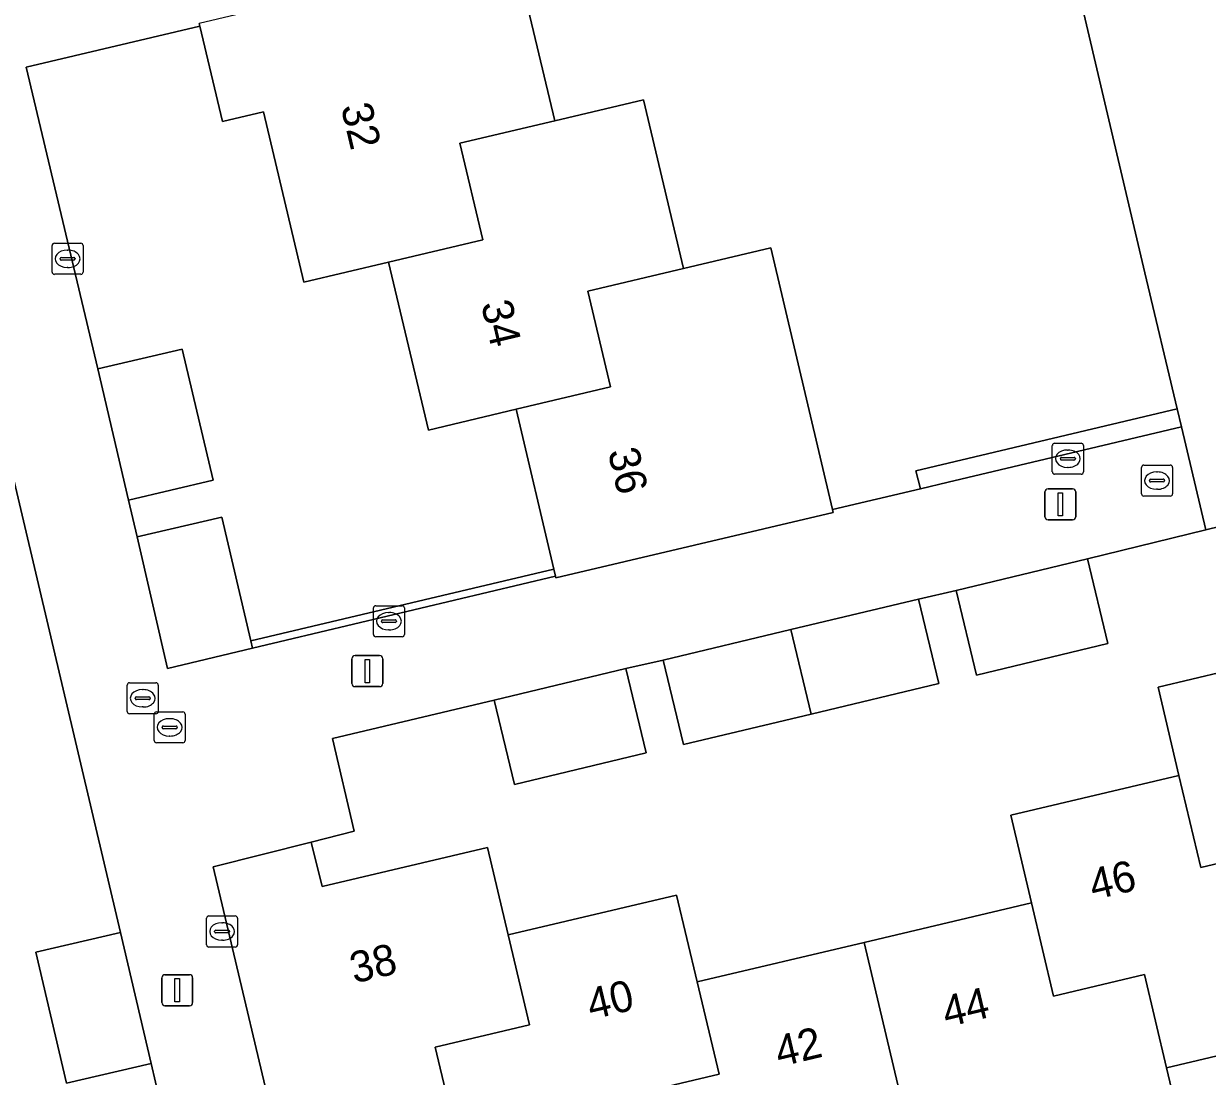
# Model space of a CAD drawing. Extents: x 158031 to 159244, y 380104 to 381214.
# Drawn here: x 158665.32 to 158703.48, y 380430.23 to 380464.17 of the extents above; entities that cross this region are included whole.
import ezdxf

# ---------------------------------------------------------------- set-up
doc = ezdxf.new("R2010")
doc.units = 0
for name, color, linetype in [('IMGEO_Erf', 7, 'Continuous'), ('IMGEO_Groenvoorziening', 7, 'Continuous'), ('IMGEO_Haag', 7, 'Continuous'), ('IMGEO_Hek', 7, 'Continuous'), ('IMGEO_Kolk', 7, 'Continuous'), ('IMGEO_Lichtmast', 7, 'Continuous'), ('IMGEO_Muur', 7, 'Continuous'), ('IMGEO_Pand', 7, 'Continuous'), ('IMGEO_Pand_nummerreeks', 7, 'Continuous'), ('IMGEO_Rioolput', 7, 'Continuous'), ('IMGEO_Voetpad_open', 7, 'Continuous')]:
    doc.layers.add(name, color=color, linetype=linetype)

msp = doc.modelspace()

# ---------------------------------------------------------------- linework, layer by layer
at = {"layer": 'IMGEO_Erf'}
for points in [[(158698.077, 380470.54), (158695.304, 380469.884), (158687.271, 380467.982), (158681.122, 380466.593), (158682.444, 380461.045), (158685.304, 380461.722), (158686.594, 380456.28), (158689.406, 380456.946), (158691.395, 380448.507), (158694.234, 380449.177), (158694.082, 380449.756), (158702.507, 380451.76), (158701.464, 380456.145)], [(158682.408, 380446.591), (158681.194, 380451.741), (158678.369, 380451.071), (158677.086, 380456.482), (158674.354, 380455.835), (158673.051, 380461.332), (158671.732, 380461.02), (158670.999, 380464.096), (158665.396, 380462.768), (158667.707, 380453.042), (158670.434, 380453.683), (158671.427, 380449.453), (158668.7, 380448.812), (158668.978, 380447.633), (158671.707, 380448.262), (158672.644, 380444.272)]]:
    msp.add_lwpolyline(points, close=True, dxfattribs=at)
for points in [[(158669.709, 380429.443), (158669.428, 380430.652), (158666.701, 380430.014), (158665.714, 380434.238), (158668.44, 380434.875), (158663.891, 380454.12), (158661.166, 380453.48), (158660.172, 380457.711), (158662.898, 380458.351), (158662.603, 380459.561), (158659.878, 380458.917), (158658.903, 380463.042), (158657.929, 380467.167)], [(158709.015, 380449.219), (158703.434, 380447.849), (158699.622, 380446.914), (158700.278, 380444.192), (158696.039, 380443.171), (158695.383, 380445.893), (158694.174, 380445.62), (158694.824, 380442.896), (158690.708, 380441.915), (158686.592, 380440.933), (158685.942, 380443.657), (158684.731, 380443.382), (158685.386, 380440.66), (158681.146, 380439.639), (158680.49, 380442.361), (158675.272, 380441.13), (158675.971, 380438.133), (158674.586, 380437.78), (158674.943, 380436.351), (158680.276, 380437.615), (158680.944, 380434.793), (158686.372, 380436.079), (158687.036, 380433.277), (158692.422, 380434.553), (158697.811, 380435.83), (158697.143, 380438.651), (158702.566, 380439.936), (158701.892, 380442.78), (158707.32, 380444.067)], [(158750.754, 380444.95), (158748.003, 380444.298), (158748.681, 380441.436), (158742.908, 380440.068), (158742.225, 380442.949), (158736.76, 380441.654), (158736.076, 380444.542), (158730.78, 380443.287), (158725.382, 380442.008), (158726.053, 380439.177), (158720.687, 380437.905), (158721.385, 380434.963), (158715.603, 380433.593), (158714.896, 380436.577), (158712.343, 380435.972), (158706.887, 380434.679), (158707.572, 380431.787), (158702.164, 380430.506), (158702.795, 380427.844)]]:
    msp.add_lwpolyline(points, dxfattribs=at)
at = {"layer": 'IMGEO_Groenvoorziening'}
msp.add_lwpolyline([(158702.646, 380451.176), (158702.507, 380451.76), (158694.082, 380449.756), (158694.234, 380449.177), (158695.123, 380449.387)], close=True, dxfattribs=at)
at = {"layer": 'IMGEO_Haag'}
msp.add_lwpolyline([(158702.646, 380451.176), (158702.507, 380451.76), (158694.082, 380449.756), (158694.234, 380449.177), (158695.123, 380449.387)], close=True, dxfattribs=at)
at = {"layer": 'IMGEO_Hek'}
msp.add_lwpolyline([(158691.395, 380448.507), (158694.234, 380449.177)], dxfattribs=at)
at = {"layer": 'IMGEO_Kolk'}
for p, q in [((158666.234, 380456.167), (158666.234, 380457.019)), ((158666.309, 380457.093), (158667.161, 380457.093)), ((158666.722, 380456.873), (158666.747, 380456.873)), ((158667.235, 380457.019), (158667.235, 380456.167)), ((158666.493, 380456.587), (158666.493, 380456.599)), ((158666.931, 380456.55), (158666.533, 380456.55)), ((158666.536, 380456.636), (158666.934, 380456.636)), ((158666.977, 380456.599), (158666.977, 380456.587)), ((158667.161, 380456.093), (158666.309, 380456.093)), ((158666.745, 380456.313), (158666.72, 380456.313)), ((158698.484, 380449.722), (158698.484, 380450.574)), ((158698.559, 380450.648), (158699.411, 380450.648)), ((158698.972, 380450.428), (158698.997, 380450.428)), ((158699.485, 380450.574), (158699.485, 380449.722)), ((158698.743, 380450.142), (158698.743, 380450.154)), ((158699.181, 380450.105), (158698.783, 380450.105)), ((158698.786, 380450.191), (158699.184, 380450.191)), ((158699.227, 380450.154), (158699.227, 380450.142)), ((158699.411, 380449.648), (158698.559, 380449.648)), ((158698.995, 380449.868), (158698.97, 380449.868)), ((158676.67, 380445.408), (158677.522, 380445.408)), ((158676.595, 380444.482), (158676.595, 380445.334)), ((158677.083, 380445.188), (158677.108, 380445.188)), ((158677.596, 380445.334), (158677.596, 380444.482)), ((158676.854, 380444.902), (158676.854, 380444.914)), ((158677.292, 380444.865), (158676.894, 380444.865)), ((158676.897, 380444.951), (158677.295, 380444.951)), ((158677.106, 380444.628), (158677.081, 380444.628)), ((158677.338, 380444.914), (158677.338, 380444.902)), ((158677.522, 380444.408), (158676.67, 380444.408)), ((158671.216, 380434.477), (158671.216, 380435.329)), ((158671.291, 380435.403), (158672.143, 380435.403)), ((158671.704, 380435.183), (158671.729, 380435.183)), ((158672.217, 380435.329), (158672.217, 380434.477)), ((158671.475, 380434.897), (158671.475, 380434.909)), ((158671.913, 380434.86), (158671.515, 380434.86)), ((158671.518, 380434.946), (158671.916, 380434.946)), ((158671.959, 380434.909), (158671.959, 380434.897)), ((158672.143, 380434.403), (158671.291, 380434.403)), ((158671.727, 380434.623), (158671.702, 380434.623))]:
    msp.add_line(p, q, dxfattribs=at)
for points in [[(158666.234, 380456.167), (158666.234, 380457.019)], [(158666.309, 380457.093), (158667.161, 380457.093)], [(158667.235, 380457.019), (158667.235, 380456.167)], [(158667.161, 380456.093), (158666.309, 380456.093)], [(158698.484, 380449.722), (158698.484, 380450.574)], [(158698.559, 380450.648), (158699.411, 380450.648)], [(158699.485, 380450.574), (158699.485, 380449.722)], [(158699.411, 380449.648), (158698.559, 380449.648)], [(158676.67, 380445.408), (158677.522, 380445.408)], [(158676.595, 380444.482), (158676.595, 380445.334)], [(158677.596, 380445.334), (158677.596, 380444.482)], [(158677.522, 380444.408), (158676.67, 380444.408)], [(158671.216, 380434.477), (158671.216, 380435.329)], [(158671.291, 380435.403), (158672.143, 380435.403)], [(158672.217, 380435.329), (158672.217, 380434.477)], [(158672.143, 380434.403), (158671.291, 380434.403)]]:
    msp.add_lwpolyline(points, dxfattribs=at)
for centre, radius, start, end in [((158666.311, 380457.017), 0.0765, 91.552, 178.448), ((158666.311, 380457.017), 0.0765, 91.552, 178.448), ((158667.159, 380457.017), 0.0765, 1.552, 88.448), ((158667.159, 380457.017), 0.0765, 1.552, 88.448), ((158666.533, 380456.596), 0.0403, 85.8775, 175.7526), ((158666.53, 380456.586), 0.0366, 178.938, 274.7102), ((158666.934, 380456.593), 0.043, 264.8664, 352.4533), ((158666.938, 380456.598), 0.0386, 1.7309, 96.639), ((158666.311, 380456.169), 0.0765, 181.552, 268.448), ((158666.311, 380456.169), 0.0765, 181.552, 268.448), ((158667.159, 380456.169), 0.0765, 271.552, 358.448), ((158667.159, 380456.169), 0.0765, 271.552, 358.448), ((158698.561, 380450.572), 0.0765, 91.552, 178.448), ((158698.561, 380450.572), 0.0765, 91.552, 178.448), ((158699.409, 380450.572), 0.0765, 1.552, 88.448), ((158699.409, 380450.572), 0.0765, 1.552, 88.448), ((158698.783, 380450.151), 0.0403, 85.8775, 175.7526), ((158698.78, 380450.141), 0.0366, 178.938, 274.7102), ((158699.184, 380450.148), 0.043, 264.8664, 352.4533), ((158699.188, 380450.153), 0.0386, 1.7309, 96.639), ((158698.561, 380449.724), 0.0765, 181.552, 268.448), ((158698.561, 380449.724), 0.0765, 181.552, 268.448), ((158699.409, 380449.724), 0.0765, 271.552, 358.448), ((158699.409, 380449.724), 0.0765, 271.552, 358.448), ((158676.672, 380445.332), 0.0765, 91.552, 178.448), ((158676.672, 380445.332), 0.0765, 91.552, 178.448), ((158677.52, 380445.332), 0.0765, 1.552, 88.448), ((158677.52, 380445.332), 0.0765, 1.552, 88.448), ((158676.894, 380444.911), 0.0403, 85.8775, 175.7526), ((158676.891, 380444.901), 0.0366, 178.938, 274.7102), ((158677.295, 380444.908), 0.043, 264.8664, 352.4533), ((158677.299, 380444.913), 0.0386, 1.7309, 96.639), ((158676.672, 380444.484), 0.0765, 181.552, 268.448), ((158676.672, 380444.484), 0.0765, 181.552, 268.448), ((158677.52, 380444.484), 0.0765, 271.552, 358.448), ((158677.52, 380444.484), 0.0765, 271.552, 358.448), ((158671.293, 380435.327), 0.0765, 91.552, 178.448), ((158671.293, 380435.327), 0.0765, 91.552, 178.448), ((158672.141, 380435.327), 0.0765, 1.552, 88.448), ((158672.141, 380435.327), 0.0765, 1.552, 88.448), ((158671.515, 380434.906), 0.0403, 85.8775, 175.7526), ((158671.512, 380434.896), 0.0366, 178.938, 274.7102), ((158671.916, 380434.903), 0.043, 264.8664, 352.4533), ((158671.92, 380434.908), 0.0386, 1.7309, 96.639), ((158671.293, 380434.479), 0.0765, 181.552, 268.448), ((158671.293, 380434.479), 0.0765, 181.552, 268.448), ((158672.141, 380434.479), 0.0765, 271.552, 358.448), ((158672.141, 380434.479), 0.0765, 271.552, 358.448)]:
    msp.add_arc(centre, radius, start, end, dxfattribs=at)
for centre, major_axis, ratio, start_param, end_param in [((158666.721, 380456.593), (-0.387, 0.002), 0.722429, 4.712389, 7.853982), ((158666.746, 380456.593), (-0.39, 0.002), 0.717154, 1.570796, 4.712389), ((158698.971, 380450.148), (-0.387, 0.002), 0.722429, 4.712389, 7.853982), ((158698.996, 380450.148), (-0.39, 0.002), 0.717154, 1.570796, 4.712389), ((158677.082, 380444.908), (-0.387, 0.002), 0.722429, 4.712389, 7.853982), ((158677.107, 380444.908), (-0.39, 0.002), 0.717154, 1.570796, 4.712389), ((158671.703, 380434.903), (-0.387, 0.002), 0.722429, 4.712389, 7.853982), ((158671.728, 380434.903), (-0.39, 0.002), 0.717154, 1.570796, 4.712389)]:
    msp.add_ellipse(centre, major_axis=major_axis, ratio=ratio, start_param=start_param, end_param=end_param, dxfattribs=at)
at = {"layer": 'IMGEO_Lichtmast'}
for p, q in [((158698.347, 380449.176), (158699.137, 380449.176)), ((158699.137, 380449.176), (158698.347, 380449.176)), ((158698.247, 380448.276), (158698.247, 380449.076)), ((158698.247, 380449.076), (158698.247, 380448.276)), ((158699.237, 380449.076), (158699.237, 380448.276)), ((158699.237, 380448.276), (158699.237, 380449.076)), ((158699.137, 380448.176), (158698.347, 380448.176)), ((158698.347, 380448.176), (158699.137, 380448.176)), ((158675.904, 380442.898), (158675.904, 380443.698)), ((158675.904, 380443.698), (158675.904, 380442.898)), ((158676.004, 380443.798), (158676.794, 380443.798)), ((158676.794, 380443.798), (158676.004, 380443.798)), ((158676.894, 380443.698), (158676.894, 380442.898)), ((158676.894, 380442.898), (158676.894, 380443.698)), ((158676.794, 380442.798), (158676.004, 380442.798)), ((158676.004, 380442.798), (158676.794, 380442.798)), ((158669.875, 380433.511), (158670.665, 380433.511)), ((158670.665, 380433.511), (158669.875, 380433.511)), ((158669.775, 380432.611), (158669.775, 380433.411)), ((158669.775, 380433.411), (158669.775, 380432.611)), ((158670.765, 380433.411), (158670.765, 380432.611)), ((158670.765, 380432.611), (158670.765, 380433.411)), ((158670.665, 380432.511), (158669.875, 380432.511)), ((158669.875, 380432.511), (158670.665, 380432.511))]:
    msp.add_line(p, q, dxfattribs=at)
for points in [[(158698.667, 380449.051), (158698.817, 380449.051), (158698.817, 380448.301), (158698.667, 380448.301), (158698.667, 380449.051)], [(158676.324, 380443.673), (158676.474, 380443.673), (158676.474, 380442.923), (158676.324, 380442.923), (158676.324, 380443.673)], [(158670.195, 380433.386), (158670.345, 380433.386), (158670.345, 380432.636), (158670.195, 380432.636), (158670.195, 380433.386)]]:
    msp.add_lwpolyline(points, dxfattribs=at)
for centre, start, end in [((158698.347, 380449.076), 90, 180), ((158698.347, 380449.076), 90, 180), ((158699.137, 380449.076), 0, 90), ((158699.137, 380449.076), 360, 90), ((158698.347, 380448.276), 180, 270), ((158698.347, 380448.276), 180, 270), ((158699.137, 380448.276), 270, 0), ((158699.137, 380448.276), 270, 0), ((158676.004, 380443.698), 90, 180), ((158676.004, 380443.698), 90, 180), ((158676.794, 380443.698), 0, 90), ((158676.794, 380443.698), 360, 90), ((158676.004, 380442.898), 180, 270), ((158676.004, 380442.898), 180, 270), ((158676.794, 380442.898), 270, 0), ((158676.794, 380442.898), 270, 0), ((158669.875, 380433.411), 90, 180), ((158669.875, 380433.411), 90, 180), ((158670.665, 380433.411), 0, 90), ((158670.665, 380433.411), 360, 90), ((158669.875, 380432.611), 180, 270), ((158669.875, 380432.611), 180, 270), ((158670.665, 380432.611), 270, 0), ((158670.665, 380432.611), 270, 0)]:
    msp.add_arc(centre, 0.1, start, end, dxfattribs=at)
at = {"layer": 'IMGEO_Muur'}
msp.add_lwpolyline([(158682.463, 380446.358), (158682.408, 380446.591), (158672.644, 380444.272), (158672.699, 380444.038)], close=True, dxfattribs=at)
at = {"layer": 'IMGEO_Pand'}
for points in [[(158677.086, 380456.482), (158680.121, 380457.202), (158679.383, 380460.32), (158682.444, 380461.045), (158681.122, 380466.593), (158670.98, 380464.176), (158670.999, 380464.096), (158671.732, 380461.02), (158673.051, 380461.332), (158674.354, 380455.835)], [(158686.594, 380456.28), (158685.304, 380461.722), (158682.444, 380461.045), (158679.383, 380460.32), (158680.121, 380457.202), (158677.086, 380456.482), (158678.369, 380451.071), (158681.194, 380451.741), (158684.236, 380452.461), (158683.505, 380455.548)], [(158686.594, 380456.28), (158683.505, 380455.548), (158684.236, 380452.461), (158681.194, 380451.741), (158682.408, 380446.591), (158682.463, 380446.358), (158682.476, 380446.302), (158691.418, 380448.409), (158691.395, 380448.507), (158689.406, 380456.946)], [(158668.7, 380448.812), (158671.427, 380449.453), (158670.434, 380453.683), (158667.707, 380453.042)], [(158672.644, 380444.272), (158671.707, 380448.262), (158668.978, 380447.633), (158669.958, 380443.388), (158672.699, 380444.038)], [(158699.622, 380446.914), (158695.383, 380445.893), (158696.039, 380443.171), (158700.278, 380444.192)], [(158702.566, 380439.936), (158703.271, 380436.962), (158706.183, 380437.652), (158706.887, 380434.679), (158712.343, 380435.972), (158710.934, 380441.953), (158709.967, 380446.035), (158707.019, 380445.336), (158707.32, 380444.067), (158701.892, 380442.78)], [(158690.708, 380441.915), (158694.824, 380442.896), (158694.174, 380445.62), (158690.058, 380444.638)], [(158690.708, 380441.915), (158690.058, 380444.638), (158685.942, 380443.657), (158686.592, 380440.933)], [(158680.49, 380442.361), (158681.146, 380439.639), (158685.386, 380440.66), (158684.731, 380443.382)], [(158702.566, 380439.936), (158697.143, 380438.651), (158697.811, 380435.83), (158698.523, 380432.822), (158701.451, 380433.515), (158702.164, 380430.506), (158707.572, 380431.787), (158706.887, 380434.679), (158706.183, 380437.652), (158703.271, 380436.962)], [(158679.304, 380428.153), (158678.587, 380431.175), (158681.63, 380431.896), (158680.944, 380434.793), (158680.276, 380437.615), (158674.943, 380436.351), (158674.586, 380437.78), (158671.429, 380436.993), (158673.821, 380426.859)], [(158687.036, 380433.277), (158686.372, 380436.079), (158680.944, 380434.793), (158681.63, 380431.896), (158678.587, 380431.175), (158679.304, 380428.153), (158679.976, 380425.321), (158685.359, 380426.597), (158684.654, 380429.572), (158687.741, 380430.303)], [(158693.841, 380428.547), (158696.348, 380429.141), (158696.982, 380426.467), (158702.795, 380427.844), (158702.164, 380430.506), (158701.451, 380433.515), (158698.523, 380432.822), (158697.811, 380435.83), (158692.422, 380434.553)], [(158668.44, 380434.875), (158665.714, 380434.238), (158666.701, 380430.014), (158669.428, 380430.652)], [(158687.036, 380433.277), (158687.741, 380430.303), (158684.654, 380429.572), (158685.359, 380426.597), (158686.021, 380423.802), (158690.887, 380424.956), (158691.808, 380425.174), (158691.159, 380427.911), (158693.841, 380428.547), (158692.422, 380434.553)]]:
    msp.add_lwpolyline(points, close=True, dxfattribs=at)
at = {"layer": 'IMGEO_Rioolput'}
for p, q in [((158701.434, 380449.941), (158702.286, 380449.941)), ((158701.359, 380449.015), (158701.359, 380449.867)), ((158701.847, 380449.721), (158701.872, 380449.721)), ((158702.36, 380449.867), (158702.36, 380449.015)), ((158701.618, 380449.435), (158701.618, 380449.447)), ((158702.056, 380449.398), (158701.658, 380449.398)), ((158701.661, 380449.484), (158702.059, 380449.484)), ((158701.87, 380449.161), (158701.845, 380449.161)), ((158702.102, 380449.447), (158702.102, 380449.435)), ((158702.286, 380448.941), (158701.434, 380448.941)), ((158668.657, 380441.996), (158668.657, 380442.848)), ((158668.732, 380442.922), (158669.584, 380442.922)), ((158669.145, 380442.702), (158669.17, 380442.702)), ((158669.658, 380442.848), (158669.658, 380441.996)), ((158668.916, 380442.416), (158668.916, 380442.428)), ((158669.354, 380442.379), (158668.956, 380442.379)), ((158668.959, 380442.465), (158669.357, 380442.465)), ((158669.4, 380442.428), (158669.4, 380442.416)), ((158669.584, 380441.922), (158668.732, 380441.922)), ((158669.168, 380442.142), (158669.143, 380442.142)), ((158669.525, 380441.06), (158669.525, 380441.912)), ((158669.6, 380441.986), (158670.452, 380441.986)), ((158670.526, 380441.912), (158670.526, 380441.06)), ((158669.827, 380441.529), (158670.225, 380441.529)), ((158670.013, 380441.766), (158670.038, 380441.766)), ((158669.784, 380441.48), (158669.784, 380441.492)), ((158670.222, 380441.443), (158669.824, 380441.443)), ((158670.036, 380441.206), (158670.011, 380441.206)), ((158670.268, 380441.492), (158670.268, 380441.48)), ((158670.452, 380440.986), (158669.6, 380440.986))]:
    msp.add_line(p, q, dxfattribs=at)
for points in [[(158701.434, 380449.941), (158702.286, 380449.941)], [(158701.359, 380449.015), (158701.359, 380449.867)], [(158702.36, 380449.867), (158702.36, 380449.015)], [(158702.286, 380448.941), (158701.434, 380448.941)], [(158668.657, 380441.996), (158668.657, 380442.848)], [(158668.732, 380442.922), (158669.584, 380442.922)], [(158669.658, 380442.848), (158669.658, 380441.996)], [(158669.584, 380441.922), (158668.732, 380441.922)], [(158669.525, 380441.06), (158669.525, 380441.912)], [(158669.6, 380441.986), (158670.452, 380441.986)], [(158670.526, 380441.912), (158670.526, 380441.06)], [(158670.452, 380440.986), (158669.6, 380440.986)]]:
    msp.add_lwpolyline(points, dxfattribs=at)
for centre, radius, start, end in [((158701.436, 380449.865), 0.0765, 91.552, 178.448), ((158701.436, 380449.865), 0.0765, 91.552, 178.448), ((158702.284, 380449.865), 0.0765, 1.552, 88.448), ((158702.284, 380449.865), 0.0765, 1.552, 88.448), ((158701.658, 380449.444), 0.0403, 85.8775, 175.7526), ((158701.655, 380449.434), 0.0366, 178.938, 274.7102), ((158702.059, 380449.441), 0.043, 264.8664, 352.4533), ((158702.063, 380449.446), 0.0386, 1.7309, 96.639), ((158701.436, 380449.017), 0.0765, 181.552, 268.448), ((158701.436, 380449.017), 0.0765, 181.552, 268.448), ((158702.284, 380449.017), 0.0765, 271.552, 358.448), ((158702.284, 380449.017), 0.0765, 271.552, 358.448), ((158668.734, 380442.846), 0.0765, 91.552, 178.448), ((158668.734, 380442.846), 0.0765, 91.552, 178.448), ((158669.582, 380442.846), 0.0765, 1.552, 88.448), ((158669.582, 380442.846), 0.0765, 1.552, 88.448), ((158668.956, 380442.425), 0.0403, 85.8775, 175.7526), ((158668.953, 380442.415), 0.0366, 178.938, 274.7102), ((158669.357, 380442.422), 0.043, 264.8664, 352.4533), ((158669.361, 380442.427), 0.0386, 1.7309, 96.639), ((158668.734, 380441.998), 0.0765, 181.552, 268.448), ((158668.734, 380441.998), 0.0765, 181.552, 268.448), ((158669.602, 380441.91), 0.0765, 91.552, 178.448), ((158669.602, 380441.91), 0.0765, 91.552, 178.448), ((158669.582, 380441.998), 0.0765, 271.552, 358.448), ((158669.582, 380441.998), 0.0765, 271.552, 358.448), ((158670.45, 380441.91), 0.0765, 1.552, 88.448), ((158670.45, 380441.91), 0.0765, 1.552, 88.448), ((158669.824, 380441.489), 0.0403, 85.8775, 175.7526), ((158670.229, 380441.491), 0.0386, 1.7309, 96.639), ((158669.821, 380441.479), 0.0366, 178.938, 274.7102), ((158670.225, 380441.486), 0.043, 264.8664, 352.4533), ((158669.602, 380441.062), 0.0765, 181.552, 268.448), ((158669.602, 380441.062), 0.0765, 181.552, 268.448), ((158670.45, 380441.062), 0.0765, 271.552, 358.448), ((158670.45, 380441.062), 0.0765, 271.552, 358.448)]:
    msp.add_arc(centre, radius, start, end, dxfattribs=at)
for centre, major_axis, ratio, start_param, end_param in [((158701.846, 380449.441), (-0.387, 0.002), 0.722429, 4.712389, 7.853982), ((158701.871, 380449.441), (-0.39, 0.002), 0.717154, 1.570796, 4.712389), ((158669.144, 380442.422), (-0.387, 0.002), 0.722429, 4.712389, 7.853982), ((158669.169, 380442.422), (-0.39, 0.002), 0.717154, 1.570796, 4.712389), ((158670.012, 380441.486), (-0.387, 0.002), 0.722429, 4.712389, 7.853982), ((158670.037, 380441.486), (-0.39, 0.002), 0.717154, 1.570796, 4.712389)]:
    msp.add_ellipse(centre, major_axis=major_axis, ratio=ratio, start_param=start_param, end_param=end_param, dxfattribs=at)
at = {"layer": 'IMGEO_Voetpad_open'}
for points in [[(158690.712, 380490.978), (158656.99, 380482.96), (158659.364, 380473.275), (158660.368, 380469.037), (158660.654, 380467.811), (158661.628, 380463.686), (158662.603, 380459.561), (158662.898, 380458.351), (158663.891, 380454.12), (158668.44, 380434.875), (158669.428, 380430.652), (158669.709, 380429.443)], [(158690.819, 380488.741), (158691.886, 380484.012), (158693.363, 380477.855), (158693.449, 380477.869), (158693.513, 380477.568), (158694.616, 380472.843), (158695.304, 380469.884), (158698.077, 380470.54), (158701.464, 380456.145), (158702.507, 380451.76), (158702.646, 380451.176), (158703.434, 380447.849), (158709.015, 380449.219), (158708.381, 380451.985), (158712.603, 380453.018), (158713.842, 380453.301), (158718.08, 380454.306), (158723.296, 380455.53), (158732.106, 380457.601), (158737.314, 380458.825), (158741.538, 380459.818), (158742.746, 380460.102), (158746.999, 380461.102), (158751.736, 380462.236)], [(158673.821, 380426.859), (158671.429, 380436.993), (158674.586, 380437.78), (158675.971, 380438.133), (158675.272, 380441.13), (158680.49, 380442.361), (158684.731, 380443.382), (158685.942, 380443.657), (158690.058, 380444.638), (158694.174, 380445.62), (158695.383, 380445.893), (158699.622, 380446.914), (158703.434, 380447.849), (158702.646, 380451.176), (158695.123, 380449.387), (158694.234, 380449.177), (158691.395, 380448.507), (158691.418, 380448.409), (158682.476, 380446.302), (158682.463, 380446.358), (158672.699, 380444.038), (158669.958, 380443.388), (158668.978, 380447.633), (158668.7, 380448.812), (158667.707, 380453.042), (158665.396, 380462.768), (158670.999, 380464.096), (158670.98, 380464.176)]]:
    msp.add_lwpolyline(points, dxfattribs=at)

# ---------------------------------------------------------------- texts
at = {"layer": 'IMGEO_Pand_nummerreeks'}
for s, rotation, p in [('32', 283.3352, (158675.54, 380461.498)), ('34', 283.3313, (158680.059, 380455.139)), ('36', 283.3323, (158684.147, 380450.381)), ('46', 13.3306, (158699.807, 380435.911)), ('38', 13.3306, (158675.974, 380433.224)), ('40', 13.3287, (158683.614, 380432.054)), ('44', 13.3297, (158695.07, 380431.81)), ('42', 13.3297, (158689.679, 380430.532))]:
    msp.add_text(s, height=1, rotation=rotation, dxfattribs=at).set_placement(p)

doc.saveas('drawing.dxf')
